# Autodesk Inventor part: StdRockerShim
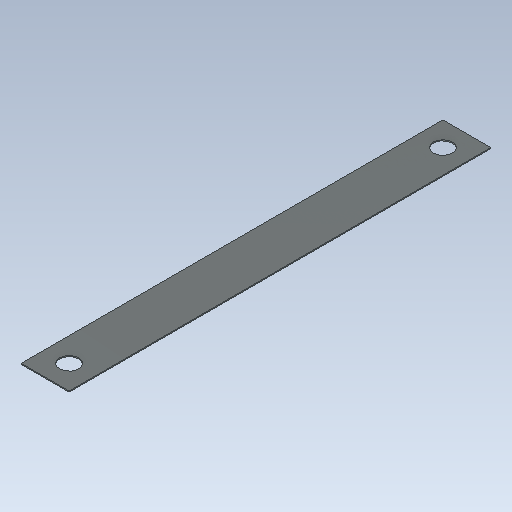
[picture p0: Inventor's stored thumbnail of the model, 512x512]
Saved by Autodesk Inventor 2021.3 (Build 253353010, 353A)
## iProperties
Created: 2019-05
Part Number: StdRockerShim
Material: Steel, Galvanized
Document SubType Name: Modeling
Designer: u1426
Density: 7.85 g/cm^3
Appearance: Galvanized
BoltDiameter: 1.500 in
MasonryEdgeDist: 2.500 in
MasonryLength: 44.000 in
MasonryWidth: 5.000 in
d71: 2.000 in
Author: u1426
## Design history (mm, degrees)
sketch "MasonryPL"
  geometry: L1 (63.5, 0)-(63.5, 2.54); L2 (63.5, 0)-(-63.5, 0); L3 (-63.5, 0)-(-63.5, 2.54); L4 (-63.5, 2.54)-(63.5, 2.54); A1 r 609.6 centre (0, -603.744) between (63.5, 2.54) and (-63.5, 2.54); 1 further point
  constraints: 8 end point, 2 point on circle, 2 vertical, 1 centre point, 1 horizontal, 1 horizontal alignment, 1 midpoint, 1 perpendicular, 1 other
  dimensions: "d84" = 609.6 radius of A1; "d89" = 2.54 distance between parallel lines of L4 L2 (= ShimThickness)
extrude "MasonryPlate" new body sketch "MasonryPL" taper "d70" = 0 deg
sketch "MasonryPLHole"
  geometry: L1 (127, -1117.6)-(127, 0) reference; L2 (0, -1117.6)-(0, 0) reference; L3 (127, 0)-(0, 0) reference; L4 (127, -1117.6)-(0, -1117.6) reference; 3 further points
  dimensions: "d79" = 63.5 distance from line of point (63.5, -63.5) L1 (derived); "d80" = 63.5 distance from line of point (63.5, -1054.1) L2 (= d79); "d90" = 63.5 distance from line of point (63.5, -63.5) L3 (derived); "d91" = 63.5 distance from line of point (63.5, -1054.1) L4 (derived)
hole "MasonryHoles" sketch "MasonryPLHole" at (63.5, -63.5), (63.5, -1054.1) stored, may be unused: countersink angle "d75" = 82 deg, drill point angle "d77" = 118 deg; dims "d72" = 19.05, "d73" = 9.525, "d74" = 6.35, "d76" = 25.4
body "Solid4"
other parameters: "ShimThickness" = 2.54 [user parameter; used in 1 equation term]
